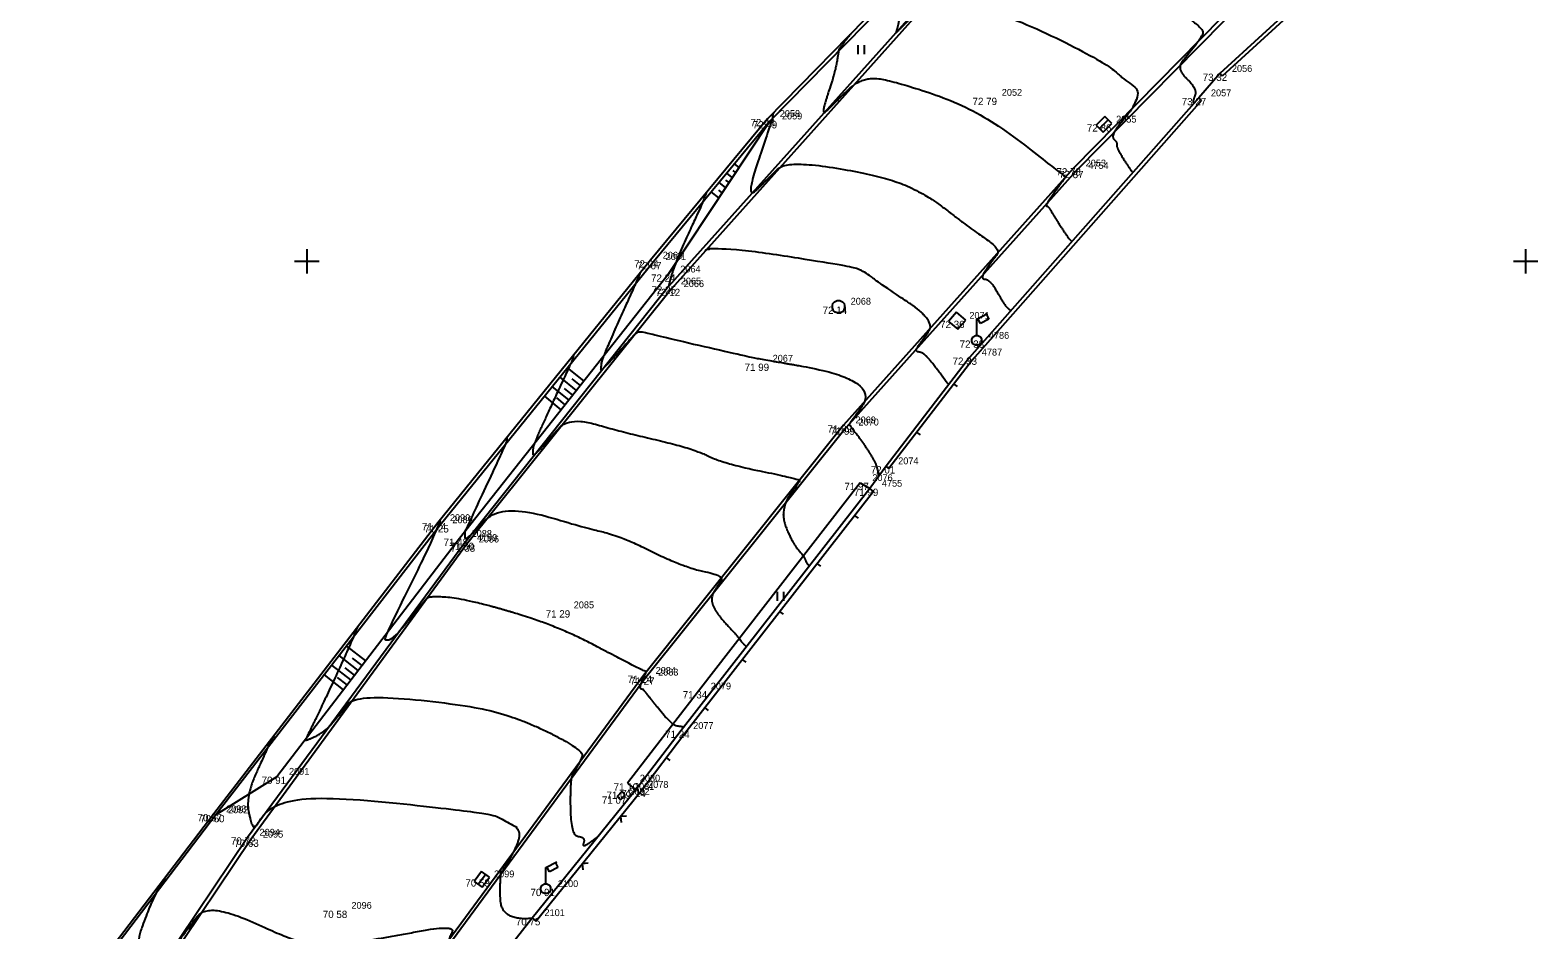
# Model space of a CAD drawing. Extents: x -704017 to -701500, y -1008977 to -1008450.
# Drawn here: x -701661.3 to -701599.5, y -1008627.4 to -1008590.5 of the extents above; entities that cross this region are included whole.
import ezdxf

# ---------------------------------------------------------------- set-up
doc = ezdxf.new("R2010")
doc.units = 0
for name, color, linetype in [('Z_body', 7, 'Continuous'), ('Z_body_cisla', 7, 'Continuous'), ('Z_body_vysky', 7, 'Continuous'), ('Z_chodnik', 7, 'Continuous'), ('Z_hekt_sit', 7, 'Continuous'), ('Z_komunikace', 7, 'Continuous'), ('Z_obruby', 7, 'Continuous'), ('Z_oploceni', 7, 'Continuous'), ('Z_popis', 7, 'Continuous'), ('Z_site_znaky_kanalizace', 7, 'Continuous'), ('Z_site_znaky_nerozlisene', 7, 'Continuous'), ('Z_site_znaky_pilire', 7, 'Continuous'), ('Z_site_znaky_VO', 7, 'Continuous'), ('Z_teren_hrany_paty', 7, 'Continuous'), ('Z_vrstevnice_hlavni', 7, 'Continuous'), ('Z_vrstevnice_vedlejsi', 7, 'Continuous'), ('Z_vstupy', 7, 'Continuous')]:
    doc.layers.add(name, color=color, linetype=linetype)

# ---------------------------------------------------------------- blocks, each defined once
blk = doc.blocks.new('POINT_DISPLAY')
blk.add_line((0, 0), (0, 0))
blk = doc.blocks.new('Z210')
blk.add_line((0, 0), (0, 0.17))
blk = doc.blocks.new('Z212')
for p, q in [((-0.17, 0.17), (0, 0)), ((0, 0), (0.17, 0.17))]:
    blk.add_line(p, q)
blk = doc.blocks.new('Z306')
for p, q in [((-0.13, 0.17), (-0.13, -0.2)), ((0.13, 0.17), (0.13, -0.2))]:
    blk.add_line(p, q)
blk = doc.blocks.new('Z13')
for p, q in [((0, 0.88), (0.45, 1.1)), ((0, 0.2), (0, 0.88)), ((0.15, 0.7), (0.05, 0.9)), ((0.5, 0.88), (0.15, 0.7)), ((0.4, 1.07), (0.5, 0.88)), ((-0.2, 0.05), (-0.15, 0.15)), ((-0.2, -0.05), (-0.2, 0.05)), ((-0.15, 0.15), (-0.05, 0.2)), ((-0.05, 0.2), (0.05, 0.2)), ((0.05, 0.2), (0.15, 0.15)), ((0.15, 0.15), (0.2, 0.05)), ((0.2, 0.05), (0.2, -0.05)), ((-0.15, -0.15), (-0.2, -0.05)), ((-0.05, -0.2), (-0.15, -0.15)), ((0.05, -0.2), (-0.05, -0.2)), ((0.15, -0.15), (0.05, -0.2)), ((0.2, -0.05), (0.15, -0.15))]:
    blk.add_line(p, q)
blk = doc.blocks.new('Z620')
for p, q in [((-0.25, 0.05), (-0.23, 0.13)), ((-0.25, -0.05), (-0.25, 0.05)), ((-0.23, 0.13), (-0.17, 0.2)), ((-0.17, 0.2), (-0.05, 0.25)), ((-0.05, 0.25), (0.05, 0.25)), ((0.05, 0.25), (0.17, 0.2)), ((0.17, 0.2), (0.23, 0.13)), ((0.23, 0.13), (0.25, 0.05)), ((0.25, 0.05), (0.25, -0.05)), ((-0.2, -0.17), (-0.25, -0.05)), ((-0.13, -0.23), (-0.2, -0.17)), ((-0.05, -0.25), (-0.13, -0.23)), ((0.05, -0.25), (-0.05, -0.25)), ((0.13, -0.23), (0.05, -0.25)), ((0.2, -0.17), (0.13, -0.23)), ((0.25, -0.05), (0.2, -0.17))]:
    blk.add_line(p, q)
blk = doc.blocks.new('Z38')
for p, q in [((0.25, 0.2), (-0.25, 0.2)), ((-0.25, 0.2), (-0.25, -0.2)), ((-0.25, 0), (0.25, 0)), ((0.25, -0.2), (0.25, 0.2)), ((-0.25, -0.2), (0.25, -0.2))]:
    blk.add_line(p, q)
blk = doc.blocks.new('Z608')
for p, q in [((0.25, 0.25), (-0.25, 0.25)), ((-0.25, 0.25), (-0.25, -0.25)), ((0.25, -0.25), (0.25, 0.25)), ((-0.25, -0.25), (0.25, -0.25))]:
    blk.add_line(p, q)

msp = doc.modelspace()

# ---------------------------------------------------------------- linework, layer by layer
at = {"layer": 'Z_chodnik'}
for p, q in [((-701626.44, -1008589.39), (-701631.1, -1008594.16)), ((-701631.1, -1008594.16), (-701635.9, -1008599.96)), ((-701635.9, -1008599.96), (-701644.63, -1008610.74)), ((-701627.3, -1008609.09), (-701633.93, -1008617.64)), ((-701627.3, -1008609.09), (-701626.91, -1008609.33)), ((-701644.63, -1008610.74), (-701653.81, -1008622.68)), ((-701633.93, -1008617.64), (-701636.84, -1008621.42)), ((-701636.84, -1008621.42), (-701636.5, -1008621.69)), ((-701653.81, -1008622.68), (-701661.35, -1008632.53))]:
    msp.add_line(p, q, dxfattribs=at)
at = {"layer": 'Z_hekt_sit'}
for p, q in [((-701650, -1008599.5), (-701650, -1008600.5)), ((-701600, -1008599.5), (-701600, -1008600.5)), ((-701650.5, -1008600), (-701649.5, -1008600)), ((-701600.5, -1008600), (-701599.5, -1008600))]:
    msp.add_line(p, q, dxfattribs=at)
at = {"layer": 'Z_komunikace'}
for p, q in [((-701609.44, -1008586.92), (-701618.55, -1008596.18)), ((-701625.12, -1008590.05), (-701635.04, -1008601.13)), ((-701618.55, -1008596.18), (-701627.99, -1008606.73)), ((-701635.04, -1008601.13), (-701643.45, -1008611.62)), ((-701627.99, -1008606.73), (-701636.19, -1008617)), ((-701643.45, -1008611.62), (-701652.3, -1008623.73)), ((-701636.19, -1008617), (-701645.08, -1008629.08)), ((-701652.3, -1008623.73), (-701659.35, -1008634.24))]:
    msp.add_line(p, q, dxfattribs=at)
at = {"layer": 'Z_obruby'}
for p, q in [((-701609.34, -1008587.05), (-701618.44, -1008596.29)), ((-701626.34, -1008589.5), (-701631.01, -1008594.25)), ((-701625.23, -1008589.95), (-701635.16, -1008601.03)), ((-701631.01, -1008594.25), (-701635.78, -1008600.03)), ((-701618.44, -1008596.29), (-701627.87, -1008606.82)), ((-701635.78, -1008600.03), (-701644.53, -1008610.83)), ((-701635.16, -1008601.03), (-701643.52, -1008611.55)), ((-701627.87, -1008606.82), (-701636.09, -1008617.08)), ((-701644.53, -1008610.83), (-701653.73, -1008622.72)), ((-701643.52, -1008611.55), (-701652.44, -1008623.64)), ((-701636.09, -1008617.08), (-701644.97, -1008629.14)), ((-701653.73, -1008622.72), (-701661.26, -1008632.59)), ((-701652.44, -1008623.64), (-701659.49, -1008634.17))]:
    msp.add_line(p, q, dxfattribs=at)
at = {"layer": 'Z_oploceni'}
for p, q in [((-701605.82, -1008586.13), (-701612.55, -1008592.3)), ((-701605.72, -1008586.24), (-701612.45, -1008592.41)), ((-701612.45, -1008592.41), (-701612.55, -1008592.3)), ((-701613.41, -1008593.3), (-701622.81, -1008603.95)), ((-701613.3, -1008593.4), (-701622.69, -1008604.05)), ((-701613.3, -1008593.4), (-701613.41, -1008593.3)), ((-701622.81, -1008603.95), (-701626.24, -1008608.41)), ((-701622.69, -1008604.05), (-701626.12, -1008608.5)), ((-701626.12, -1008608.5), (-701626.24, -1008608.41)), ((-701626.91, -1008609.33), (-701634.65, -1008619.26)), ((-701626.75, -1008609.45), (-701634.49, -1008619.38)), ((-701626.75, -1008609.45), (-701626.91, -1008609.33)), ((-701634.65, -1008619.26), (-701636.5, -1008621.69)), ((-701634.49, -1008619.38), (-701636.34, -1008621.81)), ((-701636.5, -1008621.69), (-701640.75, -1008626.95)), ((-701636.34, -1008621.81), (-701640.59, -1008627.08)), ((-701640.75, -1008626.95), (-701640.59, -1008627.08))]:
    msp.add_line(p, q, dxfattribs=at)
at = {"layer": 'Z_site_znaky_pilire'}
for p, q in [((-701637.08, -1008621.76), (-701637.27, -1008621.96)), ((-701637.13, -1008622.1), (-701637.27, -1008621.96)), ((-701636.94, -1008621.9), (-701637.13, -1008622.1)), ((-701636.94, -1008621.9), (-701637.08, -1008621.76))]:
    msp.add_line(p, q, dxfattribs=at)
at = {"layer": 'Z_teren_hrany_paty'}
for p, q in [((-701635.18, -1008600.54), (-701631.01, -1008594.25)), ((-701632.55, -1008596.57), (-701632.77, -1008596.38)), ((-701632.41, -1008596.36), (-701632.51, -1008596.27)), ((-701632.27, -1008596.15), (-701632.45, -1008596)), ((-701633.1, -1008597.4), (-701633.41, -1008597.15)), ((-701632.96, -1008597.19), (-701633.1, -1008597.08)), ((-701632.82, -1008596.98), (-701633.09, -1008596.77)), ((-701632.68, -1008596.77), (-701632.81, -1008596.67)), ((-701635.18, -1008600.54), (-701643.74, -1008611.38)), ((-701638.63, -1008604.91), (-701639.3, -1008604.37)), ((-701639.25, -1008605.69), (-701639.92, -1008605.15)), ((-701638.94, -1008605.3), (-701639.61, -1008604.76)), ((-701639.09, -1008605.5), (-701639.43, -1008605.22)), ((-701638.78, -1008605.1), (-701639.12, -1008604.83)), ((-701639.56, -1008606.09), (-701640.24, -1008605.53)), ((-701639.4, -1008605.89), (-701639.74, -1008605.61)), ((-701643.74, -1008611.38), (-701651.23, -1008621.15)), ((-701647.89, -1008616.79), (-701648.67, -1008616.18)), ((-701647.58, -1008616.39), (-701648.36, -1008615.79)), ((-701647.73, -1008616.59), (-701648.13, -1008616.29)), ((-701648.49, -1008617.58), (-701649.28, -1008616.97)), ((-701648.19, -1008617.18), (-701648.98, -1008616.58)), ((-701648.04, -1008616.99), (-701648.43, -1008616.68)), ((-701648.34, -1008617.38), (-701648.74, -1008617.08)), ((-701651.23, -1008621.15), (-701653.73, -1008622.72))]:
    msp.add_line(p, q, dxfattribs=at)
at = {"layer": 'Z_vrstevnice_hlavni'}
for points in [[(-701625.994, -1008587.219), (-701624.654, -1008587.549), (-701624.66, -1008587.598), (-701625.304, -1008588.431), (-701625.657, -1008589.777), (-701625.746, -1008590.334), (-701625.851, -1008590.643), (-701625.757, -1008590.551), (-701625.188, -1008589.988), (-701624.275, -1008589.168), (-701624.101, -1008589.016), (-701620.603, -1008590.156), (-701617.209, -1008591.87), (-701616.483, -1008592.546), (-701615.813, -1008592.969), (-701616.106, -1008593.696), (-701616.371, -1008594.02), (-701617.032, -1008594.86), (-701616.738, -1008595.137), (-701616.805, -1008595.318), (-701616.174, -1008596.319), (-701616.11, -1008596.359)], [(-701636.336, -1008600.499), (-701636.337, -1008600.51), (-701636.527, -1008600.952), (-701636.724, -1008601.377), (-701637.883, -1008603.963), (-701637.946, -1008604.39), (-701637.947, -1008604.537), (-701636.681, -1008603.147), (-701636.404, -1008602.831), (-701635.692, -1008603.037), (-701631.671, -1008603.964), (-701631.177, -1008604.044), (-701628.078, -1008604.587), (-701626.823, -1008605.426), (-701627.752, -1008606.685), (-701627.763, -1008606.7), (-701627.747, -1008606.702), (-701627.721, -1008606.736), (-701627.055, -1008607.615), (-701626.505, -1008608.58), (-701626.575, -1008608.87)], [(-701647.918, -1008615.017), (-701648.042, -1008615.233), (-701648.068, -1008615.403), (-701649.456, -1008618.418), (-701650.047, -1008619.607), (-701650.054, -1008619.686), (-701649.238, -1008619.3), (-701648.626, -1008618.541), (-701647.934, -1008617.756), (-701643.147, -1008618.229), (-701640.905, -1008618.894), (-701638.638, -1008620.087), (-701638.761, -1008620.493), (-701639.038, -1008620.937), (-701639.204, -1008621.309), (-701639.173, -1008623.583), (-701638.552, -1008623.618), (-701638.752, -1008624.161), (-701638.026, -1008623.578)]]:
    msp.add_open_spline(points, degree=2, dxfattribs=at)
at = {"layer": 'Z_vrstevnice_vedlejsi'}
for points in [[(-701625.172, -1008583.717), (-701625.088, -1008583.683), (-701624.883, -1008583.689), (-701624.878, -1008583.692), (-701621.678, -1008584.48), (-701621.694, -1008584.612), (-701622.065, -1008585.092), (-701622.426, -1008586.469), (-701622.655, -1008587.328), (-701621.636, -1008586.411), (-701620.916, -1008585.785), (-701618.953, -1008586.425), (-701617.047, -1008587.387), (-701615.024, -1008589.271), (-701613.158, -1008590.448), (-701613.328, -1008590.872), (-701613.895, -1008591.566), (-701614.323, -1008592.11), (-701613.466, -1008592.921), (-701613.662, -1008593.45), (-701613.615, -1008593.524), (-701613.61, -1008593.527)], [(-701627.699, -1008590.679), (-701628.179, -1008591.3), (-701628.186, -1008591.378), (-701628.326, -1008592.254), (-701628.954, -1008594.105), (-701628.395, -1008593.556), (-701627.228, -1008592.405), (-701625.789, -1008592.624), (-701622.372, -1008593.817), (-701619.002, -1008596.446), (-701618.868, -1008596.536), (-701618.904, -1008596.584), (-701619.726, -1008597.726), (-701619.588, -1008597.737), (-701619.439, -1008597.994), (-701618.733, -1008599.113), (-701618.61, -1008599.191)], [(-701630.848, -1008593.902), (-701630.884, -1008593.948), (-701630.901, -1008594.14), (-701630.907, -1008594.173), (-701632.057, -1008597.568), (-701631.032, -1008596.562), (-701630.328, -1008595.867), (-701626.773, -1008596.409), (-701624.756, -1008597.114), (-701622.768, -1008598.665), (-701621.52, -1008599.499), (-701621.853, -1008599.951), (-701622.405, -1008600.717), (-701621.98, -1008600.752), (-701621.521, -1008601.546), (-701621.292, -1008601.908), (-701621.11, -1008602.024)], [(-701633.609, -1008597.192), (-701633.725, -1008597.453), (-701633.736, -1008597.553), (-701635.013, -1008600.288), (-701635.16, -1008601.03)], [(-701623.667, -1008605.065), (-701624.001, -1008604.625), (-701624.673, -1008603.742), (-701625.084, -1008603.709), (-701624.803, -1008603.318), (-701624.172, -1008602.463), (-701626.533, -1008600.884), (-701627.141, -1008600.41), (-701627.757, -1008600.194), (-701633.428, -1008599.329), (-701633.669, -1008599.567)], [(-701639.065, -1008603.868), (-701639.068, -1008603.95), (-701639.195, -1008604.245), (-701640.097, -1008606.186), (-701640.699, -1008607.529), (-701640.731, -1008607.751), (-701640.733, -1008608.043), (-701640.101, -1008607.348), (-701639.245, -1008606.375), (-701637.05, -1008607.01), (-701634.188, -1008607.67), (-701632.926, -1008608.296), (-701629.756, -1008608.942), (-701629.819, -1008609.067), (-701630.61, -1008610.24), (-701630.063, -1008611.601), (-701629.615, -1008612.076), (-701629.502, -1008612.398), (-701629.387, -1008612.508)], [(-701641.793, -1008607.236), (-701641.799, -1008607.39), (-701641.862, -1008607.537), (-701643.47, -1008610.995), (-701643.515, -1008611.095), (-701643.517, -1008611.111), (-701643.52, -1008611.55), (-701642.086, -1008609.919), (-701638.409, -1008610.983), (-701637.102, -1008611.284), (-701634.526, -1008612.563), (-701632.91, -1008612.892), (-701633.085, -1008613.24), (-701633.464, -1008613.803), (-701633.202, -1008614.455), (-701632.246, -1008615.469), (-701632.202, -1008615.594), (-701631.967, -1008615.818)], [(-701634.547, -1008619.128), (-701634.578, -1008619.098), (-701635.021, -1008619.057), (-701636.178, -1008617.591), (-701636.208, -1008617.568), (-701636.318, -1008617.562), (-701636.321, -1008617.393), (-701636.157, -1008617.027), (-701636.064, -1008616.842), (-701636.126, -1008616.829), (-701636.862, -1008616.464), (-701639.737, -1008614.951), (-701643.346, -1008613.881), (-701644.984, -1008613.719), (-701645.221, -1008613.988), (-701646.379, -1008615.425), (-701646.787, -1008615.618), (-701646.762, -1008615.322), (-701644.53, -1008610.83), (-701644.521, -1008610.605)], [(-701651.344, -1008619.472), (-701651.597, -1008619.912), (-701651.607, -1008619.976), (-701652.52, -1008621.96), (-701652.249, -1008623.247), (-701652.097, -1008623.175), (-701652.031, -1008623.094), (-701650.884, -1008621.792), (-701642.948, -1008622.577), (-701642.073, -1008622.837), (-701641.188, -1008623.302), (-701641.438, -1008624.132), (-701642.004, -1008625.039), (-701642.087, -1008625.224), (-701642.061, -1008627.073), (-701640.75, -1008626.95)], [(-701655.84, -1008625.332), (-701655.816, -1008625.348), (-701656.327, -1008626.123), (-701657.173, -1008628.442), (-701655.74, -1008628.569), (-701654.892, -1008627.401), (-701654.029, -1008626.308), (-701650.45, -1008627.915), (-701649.63, -1008628.101), (-701649.047, -1008628.093), (-701646.981, -1008627.794), (-701643.95, -1008627.22), (-701644.116, -1008627.77), (-701644.97, -1008629.14), (-701643.508, -1008630.432)]]:
    msp.add_open_spline(points, degree=2, dxfattribs=at)
at = {"layer": 'Z_vstupy'}
for p, q in [((-701612.55, -1008592.3), (-701613.41, -1008593.3)), ((-701626.24, -1008608.41), (-701626.91, -1008609.33)), ((-701640.75, -1008626.95), (-701641.55, -1008627.97))]:
    msp.add_line(p, q, dxfattribs=at)

# ---------------------------------------------------------------- block references
at = {"layer": 'Z_body'}
for p in [(-701612.55, -1008592.3), (-701621.99, -1008593.29), (-701613.41, -1008593.3), (-701631.1, -1008594.16), (-701631.01, -1008594.25), (-701617.3, -1008594.38), (-701618.55, -1008596.18), (-701618.44, -1008596.29), (-701635.9, -1008599.96), (-701635.78, -1008600.03), (-701635.18, -1008600.54), (-701635.16, -1008601.03), (-701635.04, -1008601.13), (-701628.19, -1008601.86), (-701623.32, -1008602.44), (-701622.52, -1008603.25), (-701622.81, -1008603.95), (-701631.39, -1008604.2), (-701627.99, -1008606.73), (-701627.87, -1008606.82), (-701626.24, -1008608.41), (-701627.3, -1008609.09), (-701626.91, -1008609.33), (-701644.63, -1008610.74), (-701644.53, -1008610.83), (-701643.74, -1008611.38), (-701643.52, -1008611.55), (-701643.45, -1008611.62), (-701639.55, -1008614.32), (-701636.19, -1008617), (-701636.09, -1008617.08), (-701633.93, -1008617.64), (-701634.65, -1008619.26), (-701651.23, -1008621.15), (-701637.27, -1008621.96), (-701637.08, -1008621.76), (-701636.84, -1008621.42), (-701636.5, -1008621.69), (-701653.81, -1008622.68), (-701653.73, -1008622.72), (-701652.44, -1008623.64), (-701652.3, -1008623.73), (-701642.82, -1008625.36), (-701640.2, -1008625.75), (-701648.67, -1008626.65), (-701640.75, -1008626.95)]:
    msp.add_blockref('POINT_DISPLAY', p, dxfattribs=at)
at = {"layer": 'Z_oploceni'}
for name, p, rotation in [('Z210', (-701623.46, -1008605.04), -127.60000000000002), ('Z210', (-701624.98, -1008607.02), -127.60000000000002), ('Z210', (-701627.52, -1008610.44), -127.9), ('Z210', (-701629.06, -1008612.41), -127.9), ('Z210', (-701630.59, -1008614.38), -127.9), ('Z210', (-701632.13, -1008616.35), -127.9), ('Z210', (-701633.67, -1008618.33), -127.9), ('Z210', (-701635.25, -1008620.38), -127.30000000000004), ('Z212', (-701637.13, -1008622.79), -128.90000000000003), ('Z212', (-701638.7, -1008624.73), -128.90000000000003)]:
    msp.add_blockref(name, p, dxfattribs=dict(at, rotation=rotation))
at = {"layer": 'Z_popis'}
for p in [(-701627.26, -1008591.3), (-701630.58, -1008613.74)]:
    msp.add_blockref('Z306', p, dxfattribs=at)
at = {"layer": 'Z_site_znaky_kanalizace'}
for p, rotation in [((-701617.3, -1008594.38), 45), ((-701642.82, -1008625.36), 54)]:
    msp.add_blockref('Z38', p, dxfattribs=dict(at, rotation=rotation))
msp.add_blockref('Z620', (-701628.19, -1008601.86), dxfattribs=at)
at = {"layer": 'Z_site_znaky_nerozlisene', "rotation": -40.499999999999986}
msp.add_blockref('Z608', (-701623.32, -1008602.44), dxfattribs=at)
at = {"layer": 'Z_site_znaky_VO'}
for p in [(-701622.52, -1008603.25), (-701640.2, -1008625.75)]:
    msp.add_blockref('Z13', p, dxfattribs=at)

# ---------------------------------------------------------------- texts
at = {"layer": 'Z_body_cisla'}
for s, p in [('2056', (-701612.05, -1008592.23)), ('2052', (-701621.49, -1008593.21)), ('2057', (-701612.91, -1008593.23)), ('2058', (-701630.6, -1008594.08)), ('2059', (-701630.51, -1008594.18)), ('2055', (-701616.8, -1008594.31)), ('2053', (-701618.05, -1008596.11)), ('4754', (-701617.94, -1008596.21)), ('2060', (-701635.4, -1008599.89)), ('2061', (-701635.28, -1008599.95)), ('2064', (-701634.68, -1008600.46)), ('2065', (-701634.66, -1008600.95)), ('2066', (-701634.54, -1008601.06)), ('2068', (-701627.69, -1008601.78)), ('2071', (-701622.82, -1008602.36)), ('4786', (-701622.02, -1008603.18)), ('2067', (-701630.89, -1008604.12)), ('4787', (-701622.31, -1008603.87)), ('2069', (-701627.49, -1008606.65)), ('2070', (-701627.37, -1008606.74)), ('2074', (-701625.74, -1008608.33)), ('2076', (-701626.8, -1008609.02)), ('4755', (-701626.41, -1008609.25)), ('2090', (-701644.13, -1008610.66)), ('2089', (-701644.03, -1008610.75)), ('2088', (-701643.24, -1008611.31)), ('4199', (-701643.02, -1008611.48)), ('2086', (-701642.95, -1008611.54)), ('2085', (-701639.05, -1008614.24)), ('2084', (-701635.69, -1008616.93)), ('2083', (-701635.59, -1008617)), ('2079', (-701633.43, -1008617.57)), ('2077', (-701634.15, -1008619.19)), ('2091', (-701650.73, -1008621.07)), ('2080', (-701636.34, -1008621.35)), ('2078', (-701636, -1008621.61)), ('2082', (-701636.77, -1008621.89)), ('2081', (-701636.58, -1008621.69)), ('2093', (-701653.31, -1008622.61)), ('2092', (-701653.23, -1008622.65)), ('2094', (-701651.94, -1008623.57)), ('2095', (-701651.8, -1008623.65)), ('2099', (-701642.32, -1008625.28)), ('2100', (-701639.7, -1008625.68)), ('2096', (-701648.17, -1008626.57)), ('2101', (-701640.25, -1008626.87))]:
    msp.add_text(s, height=0.28, dxfattribs=at).set_placement(p)
at = {"layer": 'Z_body_vysky'}
for s, p in [('73 32', (-701613.25, -1008592.6)), ('72 79', (-701622.69, -1008593.59)), ('73 27', (-701614.11, -1008593.6)), ('72 48', (-701631.8, -1008594.46)), ('72 49', (-701631.71, -1008594.55)), ('72 86', (-701618, -1008594.68)), ('72 78', (-701619.25, -1008596.48)), ('72 87', (-701619.14, -1008596.59)), ('72 04', (-701636.575, -1008600.26)), ('72 07', (-701636.455, -1008600.33)), ('72 24', (-701635.88, -1008600.84)), ('72 25', (-701635.86, -1008601.33)), ('72 12', (-701635.69, -1008601.43)), ('72 14', (-701628.84, -1008602.16)), ('72 36', (-701624.02, -1008602.74)), ('72 38', (-701623.22, -1008603.55)), ('72 33', (-701623.51, -1008604.25)), ('71 99', (-701632.04, -1008604.5)), ('71 89', (-701628.64, -1008607.03)), ('71 99', (-701628.52, -1008607.12)), ('72 01', (-701626.865, -1008608.71)), ('71 97', (-701627.95, -1008609.39)), ('71 99', (-701627.56, -1008609.63)), ('71 24', (-701645.28, -1008611.04)), ('71 25', (-701645.18, -1008611.13)), ('71 48', (-701644.39, -1008611.68)), ('71 50', (-701644.145, -1008611.85)), ('71 38', (-701644.1, -1008611.92)), ('71 29', (-701640.2, -1008614.62)), ('71 24', (-701636.84, -1008617.3)), ('71 27', (-701636.74, -1008617.38)), ('71 34', (-701634.58, -1008617.94)), ('71 24', (-701635.3, -1008619.56)), ('70 91', (-701651.855, -1008621.45)), ('71 07', (-701637.895, -1008622.26)), ('71 09', (-701637.705, -1008622.06)), ('71 10', (-701637.415, -1008621.72)), ('71 14', (-701637.1, -1008621.99)), ('70 57', (-701654.485, -1008622.98)), ('70 60', (-701654.38, -1008623.02)), ('70 72', (-701653.115, -1008623.94)), ('70 63', (-701652.975, -1008624.03)), ('70 59', (-701643.495, -1008625.66)), ('70 91', (-701640.825, -1008626.05)), ('70 58', (-701649.345, -1008626.95)), ('70 75', (-701641.425, -1008627.25))]:
    msp.add_text(s, height=0.3, dxfattribs=at).set_placement(p)

doc.saveas('drawing.dxf')
